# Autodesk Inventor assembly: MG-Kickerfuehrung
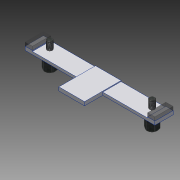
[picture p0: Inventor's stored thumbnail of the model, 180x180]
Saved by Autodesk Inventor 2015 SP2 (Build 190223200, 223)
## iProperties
Created: 2015-08
Part Number: MG-Kickerfuehrung
Document SubType Name: Assembly
Designer: rYan
Author: rYan
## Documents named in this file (5)
- E:\TIGERs GIT\Hardware\mechanik\2016\Inventor\Kicker\MG-Kickerfuehrung.iam
- E:\TIGERs GIT\Hardware\mechanik\2016\Inventor\Kicker\Kickerfuehrung.ipt
- E:\TIGERs GIT\Hardware\mechanik\2016\Inventor\Kaufteile\Abstandsbolzen Typ B M3-8mm.ipt
- D:\Tigers SVN\mechanik\2016\Inventor\Kaufteile\Abstandsbolzen Typ B.ipt
- E:\TIGERs GIT\Hardware\mechanik\2016\Inventor\Kaufteile\Gelpad 10x4.ipt
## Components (5 placed, 3 different names)
1. Kickerfuehrung:1 — Einfügen:2, Einfügen:4, Passend:1, Passend:2, Fluchtend:1, Fluchtend:2, Fluchtend:3, Fluchtend:4
2. Abstandsbolzen Typ B M3-8mm:2 — Einfügen:2
3. Abstandsbolzen Typ B M3-8mm:4 — Einfügen:4
4. Gelpad 10x4:1 — Passend:1, Fluchtend:3, Fluchtend:4
5. Gelpad 10x4:2 — Passend:2, Fluchtend:1, Fluchtend:2
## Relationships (8: Flush 4, Insert 2, Mate 2)
- Einfügen:2 [Insert]: Kickerfuehrung:1 ↔ Abstandsbolzen Typ B M3-8mm:2
- Einfügen:4 [Insert]: Kickerfuehrung:1 ↔ Abstandsbolzen Typ B M3-8mm:4
- Passend:1 [Mate]: Kickerfuehrung:1 ↔ Gelpad 10x4:1
- Passend:2 [Mate]: Kickerfuehrung:1 ↔ Gelpad 10x4:2
- Fluchtend:1 [Flush]: Kickerfuehrung:1 ↔ Gelpad 10x4:2
- Fluchtend:2 [Flush]: Kickerfuehrung:1 ↔ Gelpad 10x4:2
- Fluchtend:3 [Flush]: Kickerfuehrung:1 ↔ Gelpad 10x4:1
- Fluchtend:4 [Flush]: Kickerfuehrung:1 ↔ Gelpad 10x4:1
